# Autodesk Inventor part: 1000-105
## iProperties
Created: 2007-03
Part Number: 1000-105
Document SubType Name: Modeling
Designer: Andy Moles
Material: Steel
Mass: 27.9312 g
Surface Area: 23.9033 cm^2
Volume: 3.55812 cm^3
Density: 7.85 g/cm^3
Author: Andy Moles
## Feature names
1. Base1
